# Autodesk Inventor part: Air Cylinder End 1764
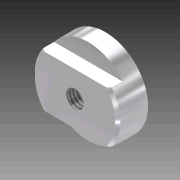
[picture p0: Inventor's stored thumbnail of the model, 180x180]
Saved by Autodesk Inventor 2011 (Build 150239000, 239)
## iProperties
Created: 2010-01
Part Number: Air Cylinder End 1764
Document SubType Name: Modeling
Designer: cmcfadden
Density: 1 g/cm^3
Author: cmcfadden
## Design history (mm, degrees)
sketch "Sketch1"
  geometry: C1 r 26.441 at (-14.977, 17.358); 1 further point
  constraints: 1 centre point
  dimensions: "d0" = 52.8828 diameter of C1
extrude "Extrusion1" new body sketch "Sketch1" distance "d1" = 18.7198; taper "d2" = 0 deg
chamfer "Chamfer1" distance "d3" = 1.5875; stored, may be unused: second distance "d4" = 3.175, angle "d5" = 45 deg
sketch "Sketch2"
  geometry: L1 (-21.145, -15.875)-(21.145, -15.875); L2 (-21.145, 15.875)-(21.145, 15.875); C1 r 24.854 at (0, 0) reference; A1 r 26.441 centre (0, 0) between (-21.145, -15.875) and (21.145, -15.875) reference; A2 r 26.441 centre (0, 0) between (21.145, 15.875) and (-21.145, 15.875); A3 r 26.441 centre (0, 0) between (-21.145, -15.875) and (21.145, -15.875); 1 further point
  constraints: 8 point on circle, 4 end point, 2 centre point, 2 concentric, 1 horizontal
  dimensions: "d6" = 31.75 distance between parallel lines of L1 L2; "d7" = 15.875 distance from line of C1.centre L2
extrude "Extrusion2" cut sketch "Sketch2" distance "d8" = 8.128; taper "d9" = 0 deg
sketch "Sketch3"
  geometry: C1 r 5.397 at (-14.977, 17.358); A1 r 24.854 centre (-14.977, 17.358) between (-34.1, 33.233) and (-34.1, 1.483) reference; 1 further point
  constraints: 1 centre point, 1 coincident
  dimensions: "d10" = 10.795 diameter of C1
extrude "Extrusion3" cut sketch "Sketch3" stored distance "d11" = 8.128; taper "d12" = 0 deg
thread "Thread1" dims "d13" = 25.4, "d14" = 0
body "Solid1"
